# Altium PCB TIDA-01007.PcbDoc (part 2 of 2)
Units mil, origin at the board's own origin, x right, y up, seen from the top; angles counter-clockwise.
Board outline 4950 x 3450 mil, 2 copper layers (Top Layer, Bottom Layer), stack 62 mil thick; 82 components, 45 nets, 235 pads, 1732 vias.
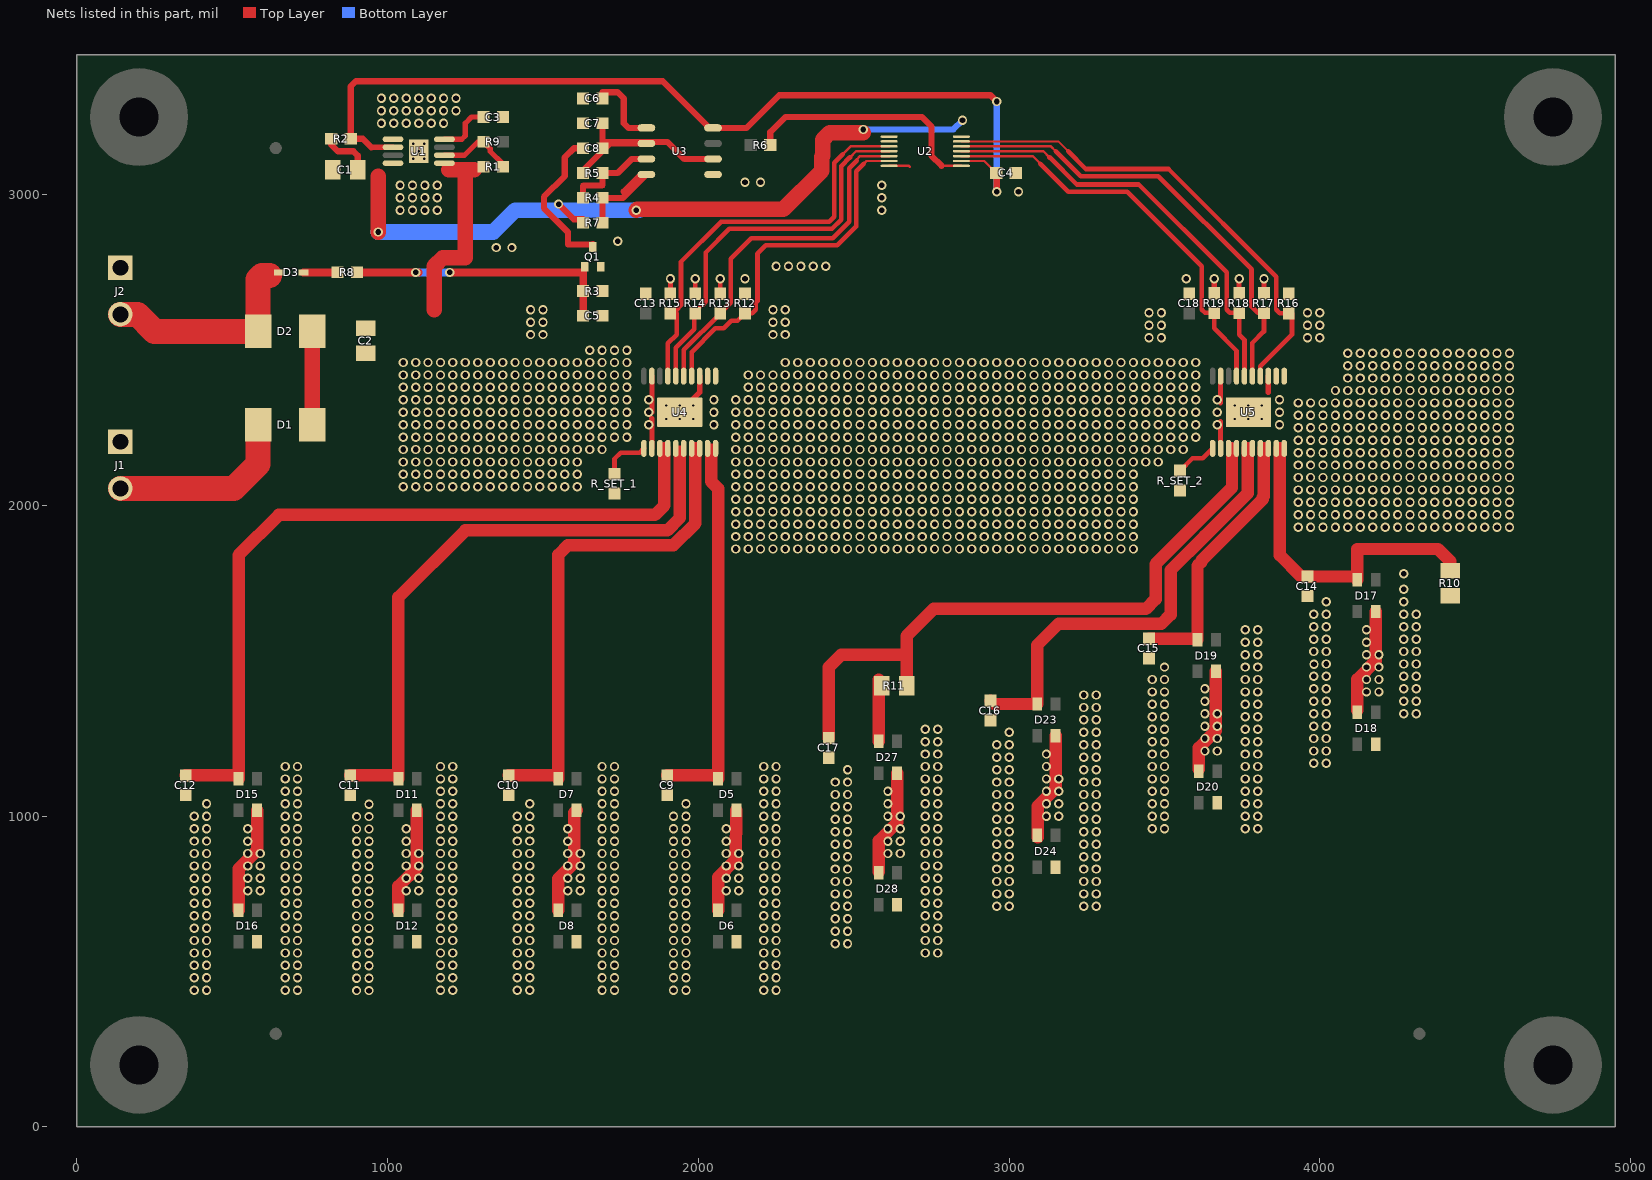
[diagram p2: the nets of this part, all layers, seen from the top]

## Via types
v1: diameter 30, hole 18, Top Layer to Bottom Layer, 1715 vias
v2: diameter 19.68, hole 7.87, Top Layer to Bottom Layer, 17 vias

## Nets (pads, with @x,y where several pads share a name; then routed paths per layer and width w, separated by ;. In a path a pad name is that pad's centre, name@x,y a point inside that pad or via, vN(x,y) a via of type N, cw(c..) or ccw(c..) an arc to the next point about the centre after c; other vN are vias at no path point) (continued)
GND: C1.2 C2.2 C3.2 C4.2 C5.2 C6.2 C7.2 C9.2 C10.2 C11.2 C12.2 C13.2 C14.2 C15.2 C16.2 C17.2 C18.2 D6.2 D8.2 D12.2 D16.2 D18.2 D20.2 D24.2 D28.2 J1.1 J2.1 Q1.2 R3.2 R10.2 R12.2 R13.2 R14.2 R15.2 R16.2 R17.2 R18.2 R19.2 R_SET_1.2 R_SET_2.2 U1.5 U1.9 U2.7 U3.1 U4.3 U4.9 U4.12 U4.21 U5.3 U5.9 U5.12 U5.21 | length 934.1
  Top Layer w7.8: U2.7@2613.86,3092.76 2677.24,3092.76 2680,3090
  Top Layer w15: R15.2@1910,2681.5 v1(1910,2730) ; R14.2@1990,2681.5 v1(1990,2730) ; R13.2@2070,2681.5 v1(2070,2730)
  Top Layer w17: 1850,2280 1850.43,2279.57 U4.12@1850.43,2183.86 ; v1@1850,2300 1850.43,2300.43 U4.9@1850.43,2416.14 ; U4.21@1940,2300 2003.98,2363.98 U4.3@2003.98,2416.14 ; R19.2@3660,2682.8 v1(3660,2730) ; U5.12@3680.43,2183.86 v1@3680.43,2270.43 ; v1@3680.43,2330.43 U5.9@3680.43,2416.14 ; R18.2@3740,2682.8 v1(3740,2730) ; R17.2@3820,2682.8 v1(3820,2730) ; 3833.98,2363.98 U5.3@3833.98,2416.14
  other v1: 900,438.98 940,438.98 377.27,440.02 417.27,440.02 670,440 710,440 1170,440 1210,440 1417.27,440.02 1457.27,440.02 1690,440 1730,440 1920,440 1960,440 2210,440 2250,440 900,478.98 940,478.98 377.27,480.02 417.27,480.02 670,480 710,480 1170,480 1210,480 1417.27,480.02 1457.27,480.02 1690,480 1730,480 1920,480 1960,480 2210,480 2250,480 900,518.98 940,518.98 377.27,520.02 417.27,520.02 670,520 710,520 1170,520 1210,520 1417.27,520.02 1457.27,520.02 1690,520 1730,520 1920,520 1960,520 2210,520 2250,520 900,558.98 940,558.98 377.27,560.02 417.27,560.02 670,560 710,560 1170,560 1210,560 1417.27,560.02 1457.27,560.02 1690,560 1730,560 1920,560 1960,560 2210,560 2250,560 2730,560 2770,560 2440,590 2480,590 900,598.98 940,598.98 377.27,600.02 417.27,600.02 670,600 710,600 1170,600 1210,600 1417.27,600.02 1457.27,600.02 1690,600 1730,600 1920,600 1960,600 2210,600 2250,600 2730,600 2770,600 2440,630 2480,630 900,638.98 940,638.98 377.27,640.02 417.27,640.02 670,640 710,640 1170,640 1210,640 1417.27,640.02 1457.27,640.02 1690,640 1730,640 1920,640 1960,640 2210,640 2250,640 2730,640 2770,640 2440,670 2480,670 900,678.98 940,678.98 377.27,680.02 417.27,680.02 670,680 710,680 1170,680 1210,680 1417.27,680.02 1457.27,680.02 1690,680 1730,680 1920,680 1960,680 2210,680 2250,680 2730,680 2770,680 2440,710 2480,710 2960,710 3000,710 3240,710 3280,710 900,718.98 940,718.98 377.27,720.02 417.27,720.02 670,720 710,720 1170,720 1210,720 1417.27,720.02 1457.27,720.02 1690,720 1730,720 1920,720 1960,720 2210,720 2250,720 2730,720 2770,720 2440,750 2480,750 2960,750 3000,750 3240,750 3280,750 900,758.98 940,758.98 377.27,760.02 417.27,760.02 670,760 710,760 1170,760 1210,760 1417.27,760.02 1457.27,760.02 1690,760 1730,760 1920,760 1960,760 2210,760 2250,760 2730,760 2770,760 2440,790 2480,790 2960,790 3000,790 3240,790 3280,790 900,798.98 940,798.98 377.27,800.02 417.27,800.02 670,800 710,800 1170,800 1210,800 1417.27,800.02 1457.27,800.02 1690,800 1730,800 1920,800 1960,800 2210,800 2250,800 2730,800 2770,800 2440,830 2480,830 2960,830 3000,830 3240,830 3280,830 900,838.98 940,838.98 377.27,840.02 417.27,840.02 670,840 710,840 1170,840 1210,840 1417.27,840.02 1457.27,840.02 1690,840 1730,840 1920,840 1960,840 2210,840 2250,840 2730,840 2770,840 2440,870 2480,870 2960,870 3000,870 3240,870 3280,870 900,878.98 940,878.98 377.27,880.02 417.27,880.02 670,880 710,880 1170,880 1210,880 1417.27,880.02 1457.27,880.02 1690,880 1730,880 1920,880 1960,880 2210,880 2250,880 2730,880 2770,880 2440,910 2480,910 2960,910 3000,910 3240,910 3280,910 900,918.98 940,918.98 377.27,920.02 417.27,920.02 670,920 710,920 1170,920 1210,920 1417.27,920.02 1457.27,920.02 1690,920 1730,920 1920,920 1960,920 2210,920 2250,920 2730,920 2770,920 2440,950 2480,950 2960,950 3000,950 3240,950 3280,950 900,958.98 940,958.98 377.27,960.02 417.27,960.02 670,960 710,960 1170,960 1210,960 1417.27,960.02 1457.27,960.02 1690,960 1730,960 1920,960 1960,960 2210,960 2250,960 2730,960 2770,960 3460,960 3500,960 3760,960 3800,960 2440,990 2480,990 2960,990 3000,990 3240,990 3280,990 900,998.98 940,998.98 377.27,1000.02 417.27,1000.02 670,1000 710,1000 1170,1000 1210,1000 1417.27,1000.02 1457.27,1000.02 1690,1000 1730,1000 1920,1000 1960,1000 2210,1000 2250,1000 2730,1000 2770,1000 3460,1000 3500,1000 3760,1000 3800,1000 2440,1030 2480,1030 2960,1030 3000,1030 3240,1030 3280,1030 940,1038.98 417.27,1040.02 670,1040 710,1040 1170,1040 1210,1040 1457.27,1040.02 1690,1040 1730,1040 1960,1040 2210,1040 2250,1040 2730,1040 2770,1040 3460,1040 3500,1040 3760,1040 3800,1040 2440,1070 2480,1070 2960,1070 3000,1070 3240,1070 3280,1070 670,1080 710,1080 1170,1080 1210,1080 1690,1080 1730,1080 2210,1080 2250,1080 2730,1080 2770,1080 3460,1080 3500,1080 3760,1080 3800,1080 2440,1110 2480,1110 2960,1110 3000,1110 3240,1110 3280,1110 670,1120 710,1120 1170,1120 1210,1120 1690,1120 1730,1120 2210,1120 2250,1120 2730,1120 2770,1120 3460,1120 3500,1120 3760,1120 3800,1120 2480,1150 2960,1150 3000,1150 3240,1150 3280,1150 670,1160 710,1160 1170,1160 1210,1160 1690,1160 1730,1160 2210,1160 2250,1160 2730,1160 2770,1160 3460,1160 3500,1160 3760,1160 3800,1160 3980,1170 4020,1170 2960,1190 3000,1190 3240,1190 3280,1190 2730,1200 2770,1200 3460,1200 3500,1200 3760,1200 3800,1200 3980,1210 4020,1210 2960,1230 3000,1230 3240,1230 3280,1230 2730,1240 2770,1240 3460,1240 3500,1240 3760,1240 3800,1240 3980,1250 4020,1250 3000,1270 3240,1270 3280,1270 2730,1280 2770,1280 3460,1280 3500,1280 3760,1280 3800,1280 3980,1290 4020,1290 3240,1310 3280,1310 3460,1320 3500,1320 3760,1320 3800,1320 3980,1330 4020,1330 4270,1330 4310,1330 3240,1350 3280,1350 3460,1360 3500,1360 3760,1360 3800,1360 3980,1370 4020,1370 4270,1370 4310,1370 3240,1390 3280,1390 3460,1400 3500,1400 3760,1400 3800,1400 3980,1410 4020,1410 4270,1410 4310,1410 3460,1440 3500,1440 3760,1440 3800,1440 3980,1450 4020,1450 4270,1450 4310,1450 3500,1480 3760,1480 3800,1480 3981,1489.08 4020,1490 4270,1490 4310,1490 3760,1520 3800,1520 3980,1530 4020,1530 4270,1530 4310,1530 3760,1560 3800,1560 3980,1570 4020,1570 4270,1570 4310,1570 3760,1600 3800,1600 3980,1610 4020,1610 4270,1610 4310,1610 3980,1650 4020,1650 4270,1650 4310,1650 4020,1690 4270,1690 4270,1730 4270,1780 2120,1860 2160,1860 2200,1860 2240,1860 2280,1860 2320,1860 2360,1860 2400,1860 2440,1860 2480,1860 2520,1860 2560,1860 2600,1860 2640,1860 2680,1860 2720,1860 2760,1860 2800,1860 2840,1860 2880,1860 2920,1860 2960,1860 3000,1860 3040,1860 3080,1860 3120,1860 3160,1860 3200,1860 3240,1860 3280,1860 3320,1860 3360,1860 3400,1860 2120,1900 2160,1900 2200,1900 2240,1900 2280,1900 2320,1900 2360,1900 2400,1900 2440,1900 2480,1900 2520,1900 2560,1900 2600,1900 2640,1900 2680,1900 2720,1900 2760,1900 2800,1900 2840,1900 2880,1900 2920,1900 2960,1900 3000,1900 3040,1900 3080,1900 3120,1900 3160,1900 3200,1900 3240,1900 3280,1900 3320,1900 3360,1900 3400,1900 3930,1930 3970,1930 4010,1930 4050,1930 4090,1930 4130,1930 4170,1930 4210,1930 4250,1930 4290,1930 4330,1930 4370,1930 4410,1930 4450,1930 4490,1930 4530,1930 4570,1930 4610,1930 2120,1940 2160,1940 2200,1940 2240,1940 2280,1940 2320,1940 2360,1940 2400,1940 2440,1940 2480,1940 2520,1940 2560,1940 2600,1940 2640,1940 2680,1940 2720,1940 2760,1940 2800,1940 2840,1940 2880,1940 2920,1940 2960,1940 3000,1940 3040,1940 3080,1940 3120,1940 3160,1940 3200,1940 3240,1940 3280,1940 3320,1940 3360,1940 3400,1940 3930,1970 3970,1970 4010,1970 4050,1970 4090,1970 4130,1970 4170,1970 4210,1970 4250,1970 4290,1970 4330,1970 4370,1970 4410,1970 4450,1970 4490,1970 4530,1970 4570,1970 4610,1970 2120,1980 2160,1980 2200,1980 2240,1980 2280,1980 2320,1980 2360,1980 2400,1980 2440,1980 2480,1980 2520,1980 2560,1980 2600,1980 2640,1980 2680,1980 2720,1980 2760,1980 2800,1980 2840,1980 2880,1980 2920,1980 2960,1980 3000,1980 3040,1980 3080,1980 3120,1980 3160,1980 3200,1980 3240,1980 3280,1980 3320,1980 3360,1980 3400,1980 3930,2010 3970,2010 4010,2010 4050,2010 4090,2010 4130,2010 4170,2010 4210,2010 4250,2010 4290,2010 4330,2010 4370,2010 4410,2010 4450,2010 4490,2010 4530,2010 4570,2010 4610,2010 2120,2020 2160,2020 2200,2020 2240,2020 2280,2020 2320,2020 2360,2020 2400,2020 2440,2020 2480,2020 2520,2020 2560,2020 2600,2020 2640,2020 2680,2020 2720,2020 2760,2020 2800,2020 2840,2020 2880,2020 2920,2020 2960,2020 3000,2020 3040,2020 3080,2020 3120,2020 3160,2020 3200,2020 3240,2020 3280,2020 3320,2020 3360,2020 3400,2020 3930,2050 3970,2050 4010,2050 4050,2050 4090,2050 4130,2050 4170,2050 4210,2050 4250,2050 4290,2050 4330,2050 4370,2050 4410,2050 4450,2050 4490,2050 4530,2050 4570,2050 4610,2050 1050,2060 1090,2060 1130,2060 1170,2060 1210,2060 1250,2060 1290,2060 1330,2060 1370,2060 1410,2060 1450,2060 1490,2060 1530,2060 1570,2060 1610,2060 2120,2060 2160,2060 2200,2060 2240,2060 2280,2060 2320,2060 2360,2060 2400,2060 2440,2060 2480,2060 2520,2060 2560,2060 2600,2060 2640,2060 2680,2060 2720,2060 2760,2060 2800,2060 2840,2060 2880,2060 2920,2060 2960,2060 3000,2060 3040,2060 3080,2060 3120,2060 3160,2060 3200,2060 3240,2060 3280,2060 3320,2060 3360,2060 3400,2060 3930,2090 3970,2090 4010,2090 4050,2090 4090,2090 4130,2090 4170,2090 4210,2090 4250,2090 4290,2090 4330,2090 4370,2090 4410,2090 4450,2090 4490,2090 4530,2090 4570,2090 4610,2090 1050,2100 1090,2100 1130,2100 1170,2100 1210,2100 1250,2100 1290,2100 1330,2100 1370,2100 1410,2100 1450,2100 1490,2100 1530,2100 1570,2100 1610,2100 2120,2100 2160,2100 2200,2100 2240,2100 2280,2100 2320,2100 2360,2100 2400,2100 2440,2100 2480,2100 2520,2100 2560,2100 2600,2100 2640,2100 2680,2100 2720,2100 2760,2100 2800,2100 2840,2100 2880,2100 2920,2100 2960,2100 3000,2100 3040,2100 3080,2100 3120,2100 3160,2100 3200,2100 3240,2100 3280,2100 3320,2100 3360,2100 3400,2100 3930,2130 3970,2130 4010,2130 4050,2130 4090,2130 4130,2130 4170,2130 4210,2130 4250,2130 4290,2130 4330,2130 4370,2130 4410,2130 4450,2130 4490,2130 4530,2130 4570,2130 4610,2130 1050,2140 1090,2140 1130,2140 1170,2140 1210,2140 1250,2140 1290,2140 1330,2140 1370,2140 1410,2140 1450,2140 1490,2140 1530,2140 1570,2140 1610,2140 2120,2140 2160,2140 2200,2140 2240,2140 2280,2140 2320,2140 2360,2140 2400,2140 2440,2140 2480,2140 2520,2140 2560,2140 2600,2140 2640,2140 2680,2140 2720,2140 2760,2140 2800,2140 2840,2140 2880,2140 2920,2140 2960,2140 3000,2140 3040,2140 3080,2140 3120,2140 3160,2140 3200,2140 3240,2140 3280,2140 3320,2140 3360,2140 3400,2140 3440,2140 3480,2140 3930,2170 3970,2170 4010,2170 4050,2170 4090,2170 4130,2170 4170,2170 4210,2170 4250,2170 4290,2170 4330,2170 4370,2170 4410,2170 4450,2170 4490,2170 4530,2170 4570,2170 4610,2170 1050,2180 1090,2180 1130,2180 1170,2180 1210,2180 1250,2180 1290,2180 1330,2180 1370,2180 1410,2180 1450,2180 1490,2180 1530,2180 1570,2180 1610,2180 1650,2180 1690,2180 2120,2180 2160,2180 2200,2180 2240,2180 2280,2180 2320,2180 2360,2180 2400,2180 2440,2180 2480,2180 2520,2180 2560,2180 2600,2180 2640,2180 2680,2180 2720,2180 2760,2180 2800,2180 2840,2180 2880,2180 2920,2180 2960,2180 3000,2180 3040,2180 3080,2180 3120,2180 3160,2180 3200,2180 3240,2180 3280,2180 3320,2180 3360,2180 3400,2180 3440,2180 3480,2180 3520,2180 3560,2180 3930,2210 3970,2210 4010,2210 4050,2210 4090,2210 4130,2210 4170,2210 4210,2210 4250,2210 4290,2210 4330,2210 4370,2210 4410,2210 4450,2210 4490,2210 4530,2210 4570,2210 4610,2210 1050,2220 1090,2220 1130,2220 1170,2220 1210,2220 1250,2220 1290,2220 1330,2220 1370,2220 1410,2220 1450,2220 1490,2220 1530,2220 1570,2220 1610,2220 1650,2220 1690,2220 1730,2220 1770,2220 2120,2220 2160,2220 2200,2220 2240,2220 2280,2220 2320,2220 2360,2220 2400,2220 2440,2220 2480,2220 2520,2220 2560,2220 2600,2220 2640,2220 2680,2220 2720,2220 2760,2220 2800,2220 2840,2220 2880,2220 2920,2220 2960,2220 3000,2220 3040,2220 3080,2220 3120,2220 3160,2220 3200,2220 3240,2220 3280,2220 3320,2220 3360,2220 3400,2220 3440,2220 3480,2220 3520,2220 3560,2220 3600,2220 3930,2250 3970,2250 4010,2250 4050,2250 4090,2250 4130,2250 4170,2250 4210,2250 4250,2250 4290,2250 4330,2250 4370,2250 4410,2250 4450,2250 4490,2250 4530,2250 4570,2250 4610,2250 1050,2260 1090,2260 1130,2260 1170,2260 1210,2260 1250,2260 1290,2260 1330,2260 1370,2260 1410,2260 1450,2260 1490,2260 1530,2260 1570,2260 1610,2260 1650,2260 1690,2260 1730,2260 1770,2260 1840,2260 2050,2260 2120,2260 2160,2260 2200,2260 2240,2260 2280,2260 2320,2260 2360,2260 2400,2260 2440,2260 2480,2260 2520,2260 2560,2260 2600,2260 2640,2260 2680,2260 2720,2260 2760,2260 2800,2260 2840,2260 2880,2260 2920,2260 2960,2260 3000,2260 3040,2260 3080,2260 3120,2260 3160,2260 3200,2260 3240,2260 3280,2260 3320,2260 3360,2260 3400,2260 3440,2260 3480,2260 3520,2260 3560,2260 3600,2260 3670,2260 3870,2260 3930,2290 3970,2290 4010,2290 4050,2290 4090,2290 4130,2290 4170,2290 4210,2290 4250,2290 4290,2290 4330,2290 4370,2290 4410,2290 4450,2290 4490,2290 4530,2290 4570,2290 4610,2290 1050,2300 1090,2300 1130,2300 1170,2300 1210,2300 1250,2300 1290,2300 1330,2300 1370,2300 1410,2300 1450,2300 1490,2300 1530,2300 1570,2300 1610,2300 1650,2300 1690,2300 1730,2300 1770,2300 1840,2300 2050,2300 2120,2300 2160,2300 2200,2300 2240,2300 2280,2300 2320,2300 2360,2300 2400,2300 2440,2300 2480,2300 2520,2300 2560,2300 2600,2300 2640,2300 2680,2300 2720,2300 2760,2300 2800,2300 2840,2300 2880,2300 2920,2300 2960,2300 3000,2300 3040,2300 3080,2300 3120,2300 3160,2300 3200,2300 3240,2300 3280,2300 3320,2300 3360,2300 3400,2300 3440,2300 3480,2300 3520,2300 3560,2300 3600,2300 3670,2300 3870,2300 3930,2330 3970,2330 4010,2330 4050,2330 4090,2330 4130,2330 4170,2330 4210,2330 4250,2330 4290,2330 4330,2330 4370,2330 4410,2330 4450,2330 4490,2330 4530,2330 4570,2330 4610,2330 1050,2340 1090,2340 1130,2340 1170,2340 1210,2340 1250,2340 1290,2340 1330,2340 1370,2340 1410,2340 1450,2340 1490,2340 1530,2340 1570,2340 1610,2340 1650,2340 1690,2340 1730,2340 1770,2340 1840,2340 2050,2340 2120,2340 2160,2340 2200,2340 2240,2340 2280,2340 2320,2340 2360,2340 2400,2340 2440,2340 2480,2340 2520,2340 2560,2340 2600,2340 2640,2340 2680,2340 2720,2340 2760,2340 2800,2340 2840,2340 2880,2340 2920,2340 2960,2340 3000,2340 3040,2340 3080,2340 3120,2340 3160,2340 3200,2340 3240,2340 3280,2340 3320,2340 3360,2340 3400,2340 3440,2340 3480,2340 3520,2340 3560,2340 3600,2340 3670,2340 3870,2340 4050,2370 4090,2370 4130,2370 4170,2370 4210,2370 4250,2370 4290,2370 4330,2370 4370,2370 4410,2370 4450,2370 4490,2370 4530,2370 4570,2370 4610,2370 1050,2380 1090,2380 1130,2380 1170,2380 1210,2380 1250,2380 1290,2380 1330,2380 1370,2380 1410,2380 1450,2380 1490,2380 1530,2380 1570,2380 1610,2380 1650,2380 1690,2380 1730,2380 1770,2380 2160,2380 2200,2380 2240,2380 2280,2380 2320,2380 2360,2380 2400,2380 2440,2380 2480,2380 2520,2380 2560,2380 2600,2380 2640,2380 2680,2380 2720,2380 2760,2380 2800,2380 2840,2380 2880,2380 2920,2380 2960,2380 3000,2380 3040,2380 3080,2380 3120,2380 3160,2380 3200,2380 3240,2380 3280,2380 3320,2380 3360,2380 3400,2380 3440,2380 3480,2380 3520,2380 3560,2380 3600,2380 4090,2410 4130,2410 4170,2410 4210,2410 4250,2410 4290,2410 4330,2410 4370,2410 4410,2410 4450,2410 4490,2410 4530,2410 4570,2410 4610,2410 1050,2420 1090,2420 1130,2420 1170,2420 1210,2420 1250,2420 1290,2420 1330,2420 1370,2420 1410,2420 1450,2420 1490,2420 1530,2420 1570,2420 1610,2420 1650,2420 1690,2420 1730,2420 1770,2420 2160,2420 2200,2420 2240,2420 2280,2420 2320,2420 2360,2420 2400,2420 2440,2420 2480,2420 2520,2420 2560,2420 2600,2420 2640,2420 2680,2420 2720,2420 2760,2420 2800,2420 2840,2420 2880,2420 2920,2420 2960,2420 3000,2420 3040,2420 3080,2420 3120,2420 3160,2420 3200,2420 3240,2420 3280,2420 3320,2420 3360,2420 3400,2420 3440,2420 3480,2420 3520,2420 3560,2420 3600,2420 4090,2450 4130,2450 4170,2450 4210,2450 4250,2450 4290,2450 4330,2450 4370,2450 4410,2450 4450,2450 4490,2450 4530,2450 4570,2450 4610,2450 1050,2460 1090,2460 1130,2460 1170,2460 1210,2460 1250,2460 1290,2460 1330,2460 1370,2460 1410,2460 1450,2460 1490,2460 1530,2460 1570,2460 1610,2460 1650,2460 1690,2460 1730,2460 1770,2460 2280,2460 2320,2460 2360,2460 2400,2460 2440,2460 2480,2460 2520,2460 2560,2460 2600,2460 2640,2460 2680,2460 2720,2460 2760,2460 2800,2460 2840,2460 2880,2460 2920,2460 2960,2460 3000,2460 3040,2460 3080,2460 3120,2460 3160,2460 3200,2460 3240,2460 3280,2460 3320,2460 3360,2460 3400,2460 3440,2460 3480,2460 3520,2460 3560,2460 3600,2460 4090,2490 4130,2490 4170,2490 4210,2490 4250,2490 4290,2490 4330,2490 4370,2490 4410,2490 4450,2490 4490,2490 4530,2490 4570,2490 4610,2490 1650,2500 1690,2500 1730,2500 1770,2500 2150,2730 3570,2730 2250,2770 2290,2770 2330,2770 2370,2770 2410,2770 1350,2830 1400,2830 1740,2850 1040,2950 1080,2950 1120,2950 1160,2950 2590,2950 1040,2990 1080,2990 1120,2990 1160,2990 2590,2990 3030,3010 1040,3030 1080,3030 1120,3030 1160,3030 2590,3030 2150,3040 2200,3040 980,3230 1020,3230 1060,3230 1100,3230 1140,3230 1180,3230 980,3270 1020,3270 1060,3270 1100,3270 1140,3270 1180,3270 1220,3270 980,3310 1020,3310 1060,3310 1100,3310 1140,3310 1180,3310 1220,3310
  other v2: 1896.69,2278.35 1940,2278.35 1983.31,2278.35 3726.69,2278.35 3770,2278.35 3813.31,2278.35 1896.69,2321.65 1940,2321.65 1983.31,2321.65 3726.69,2321.65 3770,2321.65 3813.31,2321.65 1082.28,3116.38 1117.72,3116.38 1100,3140 1082.28,3163.62 1117.72,3163.62
LDOEN: R1.2 R9.1 U1.2 | length 249.6
  Top Layer w17: U1.2@1182.68,3127.2 1247.2,3127.2 1290,3170 R9.1@1308.5,3170 1330,3148.5 1330,3140 1371.5,3098.5 R1.2@1371.5,3090
NetC3_1: C3.1 U1.4 | length 178.9
  Top Layer w17: U1.4@1182.68,3178.39 1238.39,3178.39 1250,3190 1250,3230 1270,3250 C3.1@1308.5,3250
NetC4_1: C4.1 R2.1 U1.6 U2.9 U3.4 | length 2983.8
  Top Layer w7.8: U2.9@2846.14,3108.5 2920,3108.5 C4.1@2958.5,3070
  Top Layer w17: 947.2,3152.8 U1.6@1017.32,3152.8
  Top Layer w20: 947.2,3152.8 920,3180 R2.1@881.5,3180 881.5,3348.5 897.99,3365 1885,3365 2035,3215 U3.4@2047.28,3215 2155,3215 2260,3320 2940,3320 v1(2960,3300) ; C4.1@2958.5,3070 2960,3068.5 v1(2960,3010)
  Bottom Layer w20: v1@2960,3020 v1(2960,3300)
NetC5_1: C5.1 Q1.1 R3.1 R8.2 | length 878.2
  Top Layer w25: R8.2@901.5,2750 v1(1090,2750) v1@1100,2750 ; v1(1200,2750) 1629.68,2750 R3.1@1629.68,2690 ; C5.1@1629.8,2620 R3.1@1629.8,2700
  Bottom Layer w25: v1(1090,2750) v1(1200,2750)
NetC6_1: C6.1 U3.5 | length 235.7
  Top Layer w20: 1691.5,3330 1740,3330 1760,3310 1760,3230 1775,3215 U3.5@1832.72,3215
NetC7_1: C7.1 C8.1 R5.1 U3.2 U3.6 | length 706.9
  Top Layer w20: R5.1@1628.41,3069.73 1628.41,3077.55 1715.87,3165 U3.6@1832.72,3165 ; C8.1@1691.41,3149.73 C7.1@1691.41,3229.73 ; 1691.5,3170 1900,3170 1955,3115 U3.2@2047.28,3115
NetC8_2: C8.2 Q1.3 | length 500.2
  Top Layer w20: C8.2@1628.41,3149.73 1599.73,3149.73 1570,3120 1570,3060 1503,2993 1503,2957 1580,2880 1580,2840 1660,2840 Q1.3@1660,2831.5 ; Q1.3@1660,2841.5 Q1.3@1661.3,2841.5
NetD3_1: D3.1 R8.1 | length 109.1
  Top Layer w25: D3.1@729.37,2750 R8.1@838.5,2750
NetD5_2: D5.2 D6.4 | length 344.2
  Top Layer w40: D6.4@2063.33,698.11 2063.33,803.33 2120,860 D5.2@2122.38,1018.82
  other v1: 2090,760 2130,760 2090,800 2130,800 2090,840 2130,840 2090,880 2130,880 2090,920 2090,960
NetD7_2: D7.2 D8.4 | length 345.2
  Top Layer w40: D8.4@1549.04,698.11 1549.04,799.04 1600,850 1600,1010.72 D7.2@1608.1,1018.82
  other v1: 1580,760 1620,760 1580,800 1620,800 1580,840 1620,840 1580,880 1620,880 1580,920 1580,960
NetD11_2: D11.2 D12.4 | length 345.2
  Top Layer w40: D12.4@1034.76,698.11 1034.76,774.76 1093.81,833.81 D11.2@1093.81,1018.82
  other v1: 1060,760 1100,760 1060,800 1100,800 1060,840 1100,840 1060,880 1100,880 1060,920 1060,960
NetD15_2: D15.2 D16.4 | length 345.6
  Top Layer w40: D16.4@520.47,698.11 520.47,830.47 580,890 580,1018.35 D15.2@579.53,1018.82
  other v1: 550,760 590,760 550,800 590,800 550,840 590,840 550,880 590,880 550,920 550,960
NetD17_2: D17.2 D18.4 | length 342.1
  Top Layer w40: D18.4@4120.47,1341.18 4120.47,1440.47 4179.53,1499.53 D17.2@4179.53,1658.82
  other v1: 4150,1400 4190,1400 4150,1440 4190,1440 4150,1480 4190,1480 4150,1520 4190,1520 4150,1560 4150,1600
NetD19_2: D19.2 D20.4 | length 337.5
  Top Layer w40: D20.4@3610.47,1151.18 3610.47,1220.47 3665.24,1275.24 D19.2@3665.24,1465.95
  other v1: 3630,1210 3670,1210 3630,1250 3670,1250 3630,1290 3670,1290 3630,1330 3670,1330 3630,1370 3630,1410
NetD23_2: D23.2 D24.4 | length 350.6
  Top Layer w40: D24.4@3091.9,932.1 3091.9,1031.9 3149.53,1089.53 D23.2@3149.53,1258.82
  other v1: 3120,1000 3160,1000 3120,1040 3160,1040 3120,1080 3160,1080 3120,1120 3160,1120 3120,1160 3120,1200
NetD27_2: D27.2 D28.4 | length 342.5
  Top Layer w40: D28.4@2580.47,821.18 2580.47,920.47 2640,980 2640,1138.35 D27.2@2639.53,1138.82
  other v1: 2610,880 2650,880 2610,920 2650,920 2610,960 2650,960 2610,1000 2650,1000 2610,1040 2610,1080
NetD27_4: D27.4 R11.2 | length 199
  Top Layer w40: R11.2@2580,1440 2580.47,1439.53 D27.4@2580.47,1241.18
NetR4_1: R4.1 R7.2 U3.8 | length 348
  Top Layer w20: R7.2@1691.41,2909.73 R4.1@1691.41,2989.73 1757.45,2989.73 U3.8@1832.72,3065 1815,3065 1760,3010
NetR4_2: R4.2 R5.2 U3.7 | length 301.3
  Top Layer w20: R4.2@1628.41,2989.73 1628.41,3028.23 1629.91,3029.73 1689.91,3029.73 1691.41,3031.23 R5.2@1691.41,3069.73 1739.73,3069.73 1785,3115 U3.7@1832.72,3115
NetR_SET_1_1: R_SET_1.1 U4.11 | length 157.4
  Top Layer w15: R_SET_1.1@1730,2101.5 1730,2150 1750,2170 1810.98,2170 U4.11@1824.84,2183.86
NetR_SET_2_1: R_SET_2.1 U5.11 | length 134.8
  Top Layer w15: R_SET_2.1@3550,2111.5 3590,2151.5 3622.48,2151.5 U5.11@3654.84,2183.86
OUT1: C12.1 D15.4 U4.13 U4.14 | length 2499.1
  Top Layer w40: C12.1@350,1131.5 D15.4@510.16,1131.5 ; D15.4@520.47,1121.18 520.47,1840.47 650,1970 1860,1970 1890.47,2000.47 1890.47,2183.86
OUT2: C11.1 D11.4 U4.15 U4.16 | length 1952.6
  Top Layer w40: C11.1@880,1131.5 D11.4@1024.44,1131.5 ; D11.4@1034.76,1121.18 1034.76,1704.76 1250,1920 1900,1920 1940,1960 1940,2173.61
OUT3: C10.1 D7.4 U4.17 U4.18 | length 1593.3
  Top Layer w40: C10.1@1390,1131.5 D7.4@1538.73,1131.5 ; D7.4@1549.04,1121.18 1549.04,1841.17 1580,1872.13 1919.83,1872.13 1990,1942.3 1990,2183.39 1989.53,2183.86
OUT4: C9.1 D5.4 U4.19 U4.20 | length 1235.8
  Top Layer w40: C9.1@1900,1131.5 2053.01,1131.5 D5.4@2063.33,1121.18 2063.33,2054.54 2040.71,2077.17 2040.71,2180
OUT5: C17.1 R11.1 U5.13 U5.14 | length 2092.6
  Top Layer w40: C17.1@2420,1251.5 2420,1480 2460,1520 2670,1520 ; R11.1@2670,1420 2670,1520 ; 3717.17,2183.86 3717.17,2057.17 3471.5,1811.5 3471.5,1698.74 3440,1667.24 2757.24,1667.24 2670,1580 2670,1520
OUT6: C16.1 D23.4 U5.15 U5.16 | length 1452.2
  Top Layer w40: C16.1@2940,1371.5 2950.32,1361.18 D23.4@3090.47,1361.18 3090.47,1550.47 3159.37,1619.37 3490,1619.37 3519.37,1648.74 3519.37,1791.5 3630,1902.13 3630.47,1902.13 3768.35,2040 3768.35,2183.86
OUT7: C15.1 D19.4 U5.17 U5.18 | length 856.9
  Top Layer w40: C15.1@3450,1571.5 D19.4@3603,1571.5 ; D19.4@3606.19,1568.31 3606.19,1806.19 3620,1820 3620,1823.95 3816.22,2020.17 3816.22,2026.69 3819.53,2030 3819.53,2183.86
OUT8: C14.1 D17.4 R10.1 U5.19 U5.20 | length 1048.4
  Top Layer w40: 3870.71,2183.86 3870.71,1840 3939.21,1771.5 C14.1@3960,1771.5 4101.97,1771.5 ; D17.4@4120.47,1761.18 4120.47,1860 4380,1860 4420,1820 R10.1@4420,1790
PWM1: R15.1 U2.3 U4.7 | length 1324.1
  Top Layer w7.8: 2464.25,3130 2490,3155.75 U2.3@2613.86,3155.75
  Top Layer w15: U4.7@1901.61,2416.14 1901.61,2521.61 1930,2550 1930,2618.5 ; R15.1@1910,2618.5 1921.5,2630 1930,2630 1944.07,2644.07 1944.07,2784.07 2072.87,2912.87 2420.53,2912.87 2437.13,2929.47 2437.13,3102.87 2464.25,3130
PWM2: R14.1 U2.4 U4.6 | length 1268.2
  Top Layer w7.8: 2487.65,3120 2507.65,3140 U2.4@2613.86,3140
  Top Layer w15: U4.6@1927.2,2416.14 1927.2,2507.2 1987.13,2567.13 1987.13,2618.5 R14.1@1990,2618.5 1990,2625.93 2010.51,2646.44 2015.07,2646.44 2024.07,2655.44 2024.07,2814.07 2100,2890 2430,2890 2460,2920 2460,3092.35 2487.65,3120
PWM3: R13.1 U2.5 U4.5 | length 1190.6
  Top Layer w7.8: 2510,3110 2510,3114.25 2520,3124.25 U2.5@2613.86,3124.25
  Top Layer w15: U4.5@1952.8,2416.14 1952.8,2500.45 2070,2617.65 R13.1@2070,2618.5 2104.07,2652.58 2104.07,2794.07 2170,2860 2432.35,2860 2485,2912.65 2485,3085 2510,3110
PWM4: R12.1 U2.6 U4.4 | length 1174
  Top Layer w7.8: 2532.35,3100 2540.85,3108.5 U2.6@2613.86,3108.5
  Top Layer w15: U4.4@1978.39,2416.14 1978.39,2493.69 2054.7,2570 2081.62,2570 2105.89,2594.26 2125.76,2594.26 R12.1@2150,2618.5 2173.13,2618.5 2184.63,2630 2184.63,2651.74 2190,2657.12 2190,2810 2217.13,2837.13 2447.13,2837.13 2507.87,2897.87 2507.87,3075.53 2532.35,3100
PWM5: R19.1 U2.10 U5.7 | length 1338.1
  Top Layer w7.8: U2.10@2846.14,3124.25 3075.75,3124.25 3100,3100
  Top Layer w15: 3100,3100 3190,3010 3380,3010 3620,2770 3620,2630 3630.2,2619.8 R19.1@3660,2619.8 3660,2570 3731.61,2498.39 U5.7@3731.61,2416.14
PWM6: R18.1 U2.11 U5.6 | length 1390.4
  Top Layer w7.8: U2.11@2846.14,3140 3110,3140 3130,3120
  Top Layer w15: 3130,3120 3217.13,3032.87 3417.13,3032.87 3700,2750 3700,2630 3710.2,2619.8 R18.1@3740,2619.8 3740,2550 3757.2,2532.8 U5.6@3757.2,2416.14
PWM7: R17.1 U2.12 U5.5 | length 1485.2
  Top Layer w7.8: U2.12@2846.14,3155.75 3134.25,3155.75 3150,3140
  Top Layer w15: 3150,3140 3230,3060 3480,3060 3780,2760 3780,2640 3800.2,2619.8 R17.1@3820,2619.8 3820,2560 3782.8,2522.8 U5.5@3782.8,2416.14
PWM8: R16.1 U2.13 U5.4 | length 1589.3
  Top Layer w6: U2.13@2846.14,3171.5 3158.5,3171.5 3190,3140
  Top Layer w15: 3190,3140 3247.13,3082.87 3512.83,3082.87 3860,2735.7 3860,2630 3871.5,2618.5 R16.1@3900,2618.5 ; U5.4@3808.39,2416.14 3808.39,2448.39 3910,2550 R16.1@3910,2618.5
SHIFTER_CLK: R6.1 U2.8 | length 796.7
  Top Layer w7.8: 2782.76,3092.76 U2.8@2846.14,3092.76
  Top Layer w20: R6.1@2231.5,3160 2231.5,3201.5 2280,3250 2720,3250 2750,3220 2750,3125.51 2782.76,3092.76
V_5V: C1.1 R2.2 R7.1 U1.8 U2.1 U2.2 U2.14 | length 2548.3
  Top Layer w20: R2.2@818.5,3180 818.5,3161.5 840,3140 890,3140 904.02,3125.98 C1.1@904.02,3080 ; v1(1550,2970) 1598.59,2921.41 R7.1@1628.41,2921.41 ; R7.1@1628.41,2909.73 R7.1@1628.41,2921.41 ; R7.1@1628.5,2920 1628.5,2921.41 R7.1@1628.41,2921.41
  Top Layer w50: v1(970,2880) 970,3060 ; v1(1800,2950) 1803.25,2953.25 2273.25,2953.25 2396.75,3076.75 2396.75,3122.85 2400,3126.09 2400,3177.13 2422.87,3200 v1@2530,3200
  Bottom Layer w20: v1(2530,3210) 2820,3210 v1(2850,3240)
  Bottom Layer w50: v1(970,2880) 1340,2880 1410,2950 v1(1800,2950) v1@1810,2950
V_HAZARD: D1.2 J1.2 | length 602.3
  Top Layer w80: J1.2@140,2055 505,2055 582.99,2132.99 D1.2@582.99,2260
V_IN: C2.1 D1.1 D2.1 R1.1 U1.1 U4.1 U4.2 U5.1 U5.2 | length 917.4
  Top Layer w50: D1.1@757.01,2260 D2.1@757.01,2560 ; 1150,2630 1150,2770 1177.74,2797.74 1180.04,2797.74 1180.17,2797.87 1219.83,2797.87 1219.96,2797.74 1250,2797.74 1250,3081.01 ; 1196.5,3081.01 1250,3081.01 ; 1279.01,3081.01 1250,3081.01
  other v1: 3450,2540 3490,2540 3960,2540 4000,2540 1460,2550 1500,2550 2240,2550 2280,2550 3450,2580 3490,2580 3960,2580 4000,2580 1460,2590 1500,2590 2240,2590 2280,2590 3450,2620 3490,2620 3960,2620 4000,2620 1460,2630 1500,2630 2240,2630 2280,2630
V_TURN: D2.2 D3.2 J2.2 | length 675.2
  Top Layer w80: J2.2@140,2615 195,2615 250,2560 D2.2@582.99,2560 582.99,2727.01 595.98,2740 620,2740
pads on no net: D5.1 D5.3 D6.1 D6.3 D7.1 D7.3 D8.1 D8.3 D11.1 D11.3 D12.1 D12.3 D15.1 D15.3 D16.1 D16.3 D17.1 D17.3 D18.1 D18.3 D19.1 D19.3 D20.1 D20.3 D23.1 D23.3 D24.1 D24.3 D27.1 D27.3 D28.1 D28.3 FID1.1 FID2.1 FID3.1 H1.1 H2.1 H3.1 H4.1 U1.3 U1.7 U4.10 U5.10

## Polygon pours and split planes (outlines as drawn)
GND on Top Layer "Top Layer-No Net" (solid, remove dead copper, pour order 4): 0,3450 4940,3450 4940,40 4920,20 4910,10 -10,10 -10,3480
GND on Bottom Layer "Bottom Layer-No Net" (solid, remove dead copper, pour order 6): -5,3450 15,3470 4880,3470 4880,160 4940,100 4950,90 4950,40 60,40 0,-20 20,0 20,3430

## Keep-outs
Keep-Out Layer:
  lines w10: 4950,-5 0,-5 ; 4955,0 4955,3450 ; -5,0 ccw(c0,0) 0,-5 ; -5,0 ccw(c0,0) 0,-5 ; -5,0 -5,3450 ; -5,3450 cw(c0,3450) 0,3455 ; -5,3450 cw(c0,3450) 0,3455 ; 0,3455 4950,3455 ; 4950,3455 cw(c4950,3450) 4955,3450 ; 4950,3455 cw(c4950,3450) 4955,3450
  text ".Layer_Name" at 577,-858.49 h60

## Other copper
Top Layer:
  rectangle net V_IN: 720,2530 1530,2648.58
  rectangle net V_IN: 720,2170 850,2640
  rectangle net V_5V: 889.61,3069.13 1045.85,3110
  rectangle net V_5V: 2500,3170 2641.42,3200
  rectangle net OUT1: 1871.2,2160 1900,2204.31
  rectangle net OUT2: 1932.03,2160 1950,2204.31
  rectangle net OUT3: 1983.21,2160 2000,2204.31
  rectangle net OUT4: 2034.39,2160 2050,2204.31
  rectangle net OUT5: 3701.2,2160 3730,2204.31
  rectangle net OUT6: 3762.03,2160 3780,2204.31
  rectangle net OUT7: 3813.21,2160 3830,2204.31
  rectangle net OUT8: 3864.39,2160 3880,2204.31
  rectangle net V_IN: 2200,2530 3500,2640
  rectangle net V_IN: 3940,2390 4020,2650
  rectangle net V_IN: 3860,2380 4010,2453.54
  rectangle net V_IN: 2030,2390 2120,2453.54
  rectangle net V_IN: 2150,2500 2240,2580
  rectangle net V_5V: 2820,3190 2880,3260
  rectangle net NetD15_2: 469.29,739.45 630.71,977.48
  rectangle net NetD11_2: 980,740 1130,970
  rectangle net NetD7_2: 1510,739.45 1650,977.48
  rectangle net NetD5_2: 2000,739.45 2170,977.48
  rectangle net NetD27_2: 2529.29,862.52 2690.71,1097.48
  rectangle net NetD23_2: 3050,973.44 3190,1217.48
  rectangle net NetD19_2: 3555,1192.52 3710,1424.61
  rectangle net NetD17_2: 4069.29,1382.52 4220,1617.48
  rectangle net GND: 2576.46,3030 2680,3090
  rectangle net V_IN: 2040,2430 2120,2520
  rectangle net V_IN: 2080,2480 2240,2550
  text ".Layer_Name" at 577,-858.49 h60
Bottom Layer:
  rectangle net V_IN: 1430,2540 2300,2650
  rectangle net V_IN: 3430,2530 4020,2640
  rectangle net NetD15_2: 470,680 630.71,1040
  rectangle net NetD11_2: 983.58,680 1140,1040
  rectangle net NetD7_2: 1497.86,680 1650,1040
  rectangle net NetD5_2: 2010,680 2173.57,1040
  rectangle net NetD27_2: 2520,800 2690.71,1160
  rectangle net NetD23_2: 3039.29,910 3190,1280
  rectangle net NetD19_2: 3555,1130 3710,1490
  rectangle net NetD17_2: 4069.29,1320 4220,1680
  text ".Layer_Name" at 577,-858.49 h60

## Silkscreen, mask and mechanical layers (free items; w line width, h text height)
Top Overlay:
  circle w10: c1150,3069.13 r9.13
  circle w10: c2040,3010 r9.13
  circle w10: c2610,3239.13 r9.13
  circle w10: c2100,2369.13 r9.13
  circle w10: c3930,2379.13 r9.13
  text "This document can handle board shapes up to 7.9in x 10in, although" at 220,6725 h60
  text "our panel vendors top out at 7in x 10in." at 220,6600.94 h60
  text "To re-size the board shape, do the following:" at 275,6476.88 h60
  text "Select lines on M1 Board Outline and delete (easy in single layer mode...shift+s)" at 335,6352.82 h60
  text "Draw a rectangle using lines (example will be for a 4\" x 6\" board" at 335,6228.76 h60
  text "Enter Place Line mode (keyboard pl)" at 545,6104.71 h60
  text "keyboard jo to jump to origin, hit enter" at 545,5980.65 h60
  text "keyboard jl to jump to location, set x to 6000, hit enter twice" at 545,5856.59 h60
  text "keyboard jl to jump to location, set x to 6000 and y to 4000, hit enter twice" at 545,5732.53 h60
  text "keyboard jl to jump to location, set x to 0 and y to 4000, hit enter twice" at 545,5608.47 h60
  text "keyboard jo to jump to origin, hit enter" at 545,5484.41 h60
  text "Hit ESC twice to exit place line mode" at 545,5360.35 h60
  text "Select lines on M1 Board Outline" at 335,5216.3 h60
  text "Menu Design|Board Shape|Define from Selected Objects (keyboard dsd)" at 335,5112.24 h60
  text "To define a Keep-Out that mirrors the board outline:" at 220,4988.18 h60
  text "Menu Design|Board Shape|Create Primitives From Board Shape (keyboard dsp)" at 335,4864.12 h60
  text "Set the Keep-Out Layer as the layer, set width as preferred" at 545,4740.06 h60
  text "Ensure Route Tool Outline is selected, hit enter" at 545,4616 h60
  text "If you re-size the board, don't forget to move the drill table strings on the" at 220,4293 h60
  text "Drill Drawing Layer...they should be just to the right of your board shape" at 413,4187 h60
  text "GND" at 4370,3360 h40
  text "555_CLK_OUT" at 2200,3300 h40
  text "GND" at 330,2750 h40
  text "V_TURN" at 140,2420 h40
  text "GND" at 330,2200 h40
  text "V_HAZARD" at 120,1850 h40
  text "CH5_OPEN" at 2520,1570 h40
  text "CH8_SHORT_GND" at 4560,1390 h40 r90
  text "TI Design" at 800,220 h60
  text "Sequential Turn TPS92638-Q1" at 810,80 h60
  text ".Layer_Name" at 577,-858.49 h60
Bottom Overlay:
  text ".Layer_Name" at 577,-858.49 h60
Top Paste:
  text ".Layer_Name" at 577,-858.49 h60
Bottom Paste:
  text ".Layer_Name" at 577,-858.49 h60
Top Solder:
  text ".Layer_Name" at 577,-858.49 h60
  text ".Layer_Name" at 577,-858.49 h60
Bottom Solder:
  text ".Layer_Name" at 577,-858.49 h60
Drill Guide:
  text ".Layer_Name" at 577,-858.49 h60
M1 Board Outline:
  the board outline again, w10
  text ".Layer_Name" at 577,-858.49 h60
M2 Board Dimensions:
  rectangle: 0,-275 125,-150
  rectangle: 125,-400 500,-275
  lines w7: 0,-275 1000,-275 ; 125,-400 125,-150 ; 250,-400 250,-150 ; 500,-400 500,-150 ; 750,-400 750,-150 ; 0,-400 1000,-400 1000,-150 0,-150 0,-400
  text ".Layer_Name" at 577,-858.49 h60
M3 3D STEP Top:
  text ".Layer_Name" at 577,-858.49 h60
M4 3D STEP Bottom:
  text ".Layer_Name" at 577,-858.49 h60
M5 Assembly Top:
  lines w10: -292,-930.17 6308,-930.17 ; -292,-726.83 6310,-726.83 ; -292,-523.5 -292,-1133.5 3713,-1133.5 6310,-1133.5 6310,-523.5 -291.5,-523.5 -291.5,-1133.5 1284,-1133.5 ; 2173,-1133.5 2173,-523.5 ; 3440,-726.83 3440,-523.5 ; 4280,-726.83 4280,-523.5 ; 4902,-1140 4902,-937.17
  text "COMPONENTS MARKED 'DNP' SHOULD NOT BE POPULATED." at 1153.5,-318.5 h60
  text "ASSEMBLY VARIANT:" at 1153,-434 h60
  text ".VariantName" at 2189,-434 h60
  text "PCB VIEWED FROM TOP SIDE" at -228.5,-655.67 h60
  text "BOARD #:" at 2248,-655.67 h60
  text ".PRJ_Number" at 2793.5,-655.67 h60
  text "REV:" at 3638,-655.67 h60
  text ".PCB_Rev" at 3929.5,-655.67 h60
  text "SVN REV:" at 4476,-655.67 h60
  text ".VersionControl_RevNumber" at 4982,-655.67 h60
  text "TID #:" at 2248,-859 h60
  text ".TID" at 2793.5,-859 h60
  text "PLOT NAME =" at -228.5,-1064.34 h60
  text ".plot_File_Name" at 577,-1064.34 h60
  text "GENERATED    :" at 2250,-1064.34 h60
  text ".Print_Date" at 3119.5,-1064.34 h60
  text ".Print_Time" at 3848.5,-1064.34 h60
  text "TEXAS INSTRUMENTS" at 5113,-1064.34 h60
M6 Assembly Bottom:
  lines w10: -292.5,-727.33 6309.5,-727.33 ; -290.5,-930.67 6309.5,-930.67 ; 1115.5,-1140.5 1115.5,-937.67 ; 1737.5,-727.33 1737.5,-524 ; 2577.5,-727.33 2577.5,-524 ; 3844.5,-1134 3844.5,-524 ; 4733.5,-1134 6309,-1134 6309,-524 -292.5,-524 -292.5,-1134 2304.5,-1134 6309.5,-1134 6309.5,-524
  text "COMPONENTS MARKED 'DNP' SHOULD NOT BE POPULATED." at 6102,-318 h60
  text ".VariantName" at 5058,-434 h60
  text "ASSEMBLY VARIANT:" at 6097,-434 h60
  text ".VersionControl_RevNumber" at 1035.5,-656.17 h60
  text "SVN REV:" at 1541.5,-656.17 h60
  text ".PCB_Rev" at 2088,-656.17 h60
  text "REV:" at 2379.5,-656.17 h60
  text ".PRJ_Number" at 3224,-656.17 h60
  text "BOARD #:" at 3769.5,-656.17 h60
  text "PCB VIEWED FROM BOTTOM SIDE" at 6246,-656.17 h60
  text ".TID" at 3224,-859.5 h60
  text "TID #:" at 3769.5,-859.5 h60
  text "TEXAS INSTRUMENTS" at 904.5,-1064.84 h60
  text ".Print_Time" at 2169,-1064.84 h60
  text ".Print_Date" at 2898,-1064.84 h60
  text "GENERATED    :" at 3767.5,-1064.84 h60
  text ".plot_File_Name" at 5440.5,-1064.84 h60
  text "PLOT NAME =" at 6246,-1064.84 h60
M9 Title Sheet:
  drawing of 57 lines, arcs and shapes, not listed
  text "1" at 739.84,8036.5 h70
  text "2" at 3235.5,8036.5 h70
  text "3" at 5724.84,8036.5 h70
  text "4" at 8231.51,8036.5 h70
  text "5" at 10730.5,8036.5 h70
  text "6" at 13235.5,8036.5 h70
  text "A" at -416.5,6893.5 h70
  text "A" at 14383.5,6893.5 h70
  text "B" at -416.5,4513.5 h70
  text "B" at 14383.5,4513.5 h70
  text "C" at -416.5,2138.5 h70
  text "C" at 14383.5,2138.5 h70
  text "PROJECT TITLE:" at 11343.5,277.5 h45
  text ".TIDA-01007" at 11393.5,144.17 h70
  text "DESIGNED FOR:" at 11343.5,-23.5 h45
  text ".PRJ_Customer" at 11393.5,-163.5 h70
  text "D" at -416.5,-231.5 h70
  text "D" at 14383.5,-231.5 h70
  text "FILE NAME:" at 11343.5,-323.5 h45
  text ".PCB_File_Name_No_Path" at 11393.5,-443.5 h70
  text "Texas Instruments (TI) and/or its licensors do not warrant the accuracy or completeness of this specification" at 6374,-605.34 h45
  text "ENGINEER:" at 11343.5,-613.5 h45
  text "LAYOUT BY:" at 12848.5,-613.5 h45
  text "or any information contained therein. TI and/or its licensors do not warrant that this design will meet" at 6329.01,-718 h45
  text ".Summer Su" at 11393.5,-768.49 h70
  text ".PCB_Layout" at 12899,-768.49 h70
  text "the specifications, will be suitable for your application or fit for any particular purpose, or will operate in" at 6329.01,-830.67 h45
  text ".Layer_Name" at 577,-858.49 h60
  text "ALTIUM DESIGNER VERSION:" at 12848.5,-923.5 h45
  text "an implementation. TI and/or its licensors do not warrant that the design is production worthy. You should" at 6329.01,-943.33 h45
  text "completely validate and test your design implementation to confirm the system functionality for your application." at 6374,-1056 h45
  text ".print_Scale" at 11393.5,-1056.83 h70
  text ".Application_BuildNumber" at 12899,-1056.83 h70
  text "1" at 739.84,-1263.5 h70
  text "2" at 3235.5,-1263.5 h70
  text "3" at 5724.84,-1263.5 h70
  text "4" at 8231.51,-1263.5 h70
  text "5" at 10730.5,-1263.5 h70
  text "6" at 13235.5,-1263.5 h70
M10 Fab Notes:
  drawing of 185 lines, arcs and shapes, not listed
  text "DESIGN INFORMATION" at 12381.02,5910 h60
  text "MIN. TRACK WIDTH:" at 11736.46,5730 h60
  text "8" at 12832.7,5730 h60
  text "MIL" at 12987.46,5730 h60
  text "MIN. CLEARANCE:" at 11736.46,5598 h60
  text "0.2" at 12772.7,5598 h60
  text "mm" at 12987.46,5598 h60
  text "MIN. VIA PAD SIZE:" at 11736.46,5466 h60
  text "24" at 12802.71,5466 h60
  text "MIL" at 12987.46,5466 h60
  text "0.05mm (2MIL)" at 12431.46,5324.29 h60
  text "MINIMUM ANNULAR RING" at 11407.23,5320 h60
  text "EXTERNAL" at 13139.46,5320 h60
  text "PER" at 11607.23,5202 h60
  text "IPC-D-275 CLASS 2 LEVEL C" at 11827.23,5202 h60
  text "MIL, HOLES" at 13315.46,5089.71 h60
  text "+/-" at 12923,5089 h60
  text "+/-" at 13777,5089 h60
  text "REGISTRATION TOLERANCES:" at 11407.23,5084 h60
  text "METAL" at 12607,5084 h60
  text "5" at 13183.2,5084 h60
  text "3" at 14016.2,5084 h60
  text "MIL" at 14132.46,5084 h60
  text "MATERIAL:" at 11332.46,4874.54 h60
  text "FR-4 High Tg" at 12318.9,4734.21 h60
  text "FR-408" at 11753.46,4725.64 h60
  text "X" at 12165.46,4725.64 h60
  text "OTHER" at 13241.46,4725.64 h60
  text "62 MIL (1.6mm) +/-10%" at 12073.56,4562.92 h60
  text "THICKNESS:" at 11407.23,4558.64 h60
  text "X" at 11945.4,4558.64 h60
  text "OTHER" at 13358.46,4558.64 h60
  text "TOLERANCE:" at 11407.23,4400.64 h60
  text "X" at 12246.53,4400.64 h60
  text "ANSI IPC-6012 TYPE 3 CLASS 2" at 12433.48,4400.64 h60
  text "OTHER +/-" at 12433.46,4244.64 h60
  text "BOW & TWIST:" at 11407.23,4087.64 h60
  text "X" at 12246.53,4087.64 h60
  text "ANSI IPC-6012 TYPE 3 CLASS 2" at 12433.48,4087.64 h60
  text "OTHER +/-" at 12433.46,3929.13 h60
  text "DRILLING:" at 11332.46,3790.64 h60
  text "REFERENCE:" at 11407.23,3673.64 h60
  text "X" at 12055.46,3673.64 h60
  text "AS SHOWN" at 12242.46,3673.64 h60
  text "X" at 12956.46,3673.64 h60
  text "NC_DRILL FILES" at 13093.46,3673.64 h60
  text "PTH MIN COPPER THICKNESS:" at 11407.23,3515.64 h60
  text "X" at 12757.46,3515.64 h60
  text "1MIL" at 12894.46,3515.64 h60
  text "OTHER" at 13391.46,3515.64 h60
  text "BOARD FINISH:" at 11332.46,3356.64 h60
  text "SILKSCREEN:" at 11487.68,3238.64 h60
  text "X" at 12436.46,3238.64 h60
  text "TOP" at 12562.46,3238.64 h60
  text "X" at 12946.46,3238.64 h60
  text "BOTTOM" at 13073.46,3238.64 h60
  text "SILKSCREEN COLOR:" at 11487.68,3071.64 h60
  text "X" at 12435.42,3071.64 h60
  text "WHITE" at 12562.46,3071.64 h60
  text "OTHER" at 13073.46,3071.64 h60
  text "SOLDER RESIST COLOR:" at 11487.68,2901.64 h60
  text "X" at 12650,2750 h60
  text "GREEN" at 12182.46,2742.44 h60
  text "BLUE" at 12773.46,2742.44 h60
  text "OTHER" at 13311.46,2742.44 h60
  text "IMMERSION GOLD (ENIG)" at 12393.46,2553.92 h60
  text "ENEPIG" at 13731,2550.64 h60
  text "SURFACE FINISH:" at 11332.46,2549.64 h60
  text "X" at 12206.51,2549.64 h60
  text "IMM. TIN/SILVER OR EQUIV" at 11662,2392.64 h60
  text "OTHER" at 13093.46,2392.64 h60
  text "ARRAY/PANEL:" at 11332.46,2213.64 h60
  text "CUT AND TRIM PER MECH LAYER 1" at 12393.46,2209.35 h60
  text "N.C. ROUTE" at 12393.46,2057.64 h60
  text "X" at 13072.46,2057.64 h60
  text "V. SCORE" at 13259.46,2057.64 h60
  text "CERTIFICATION:" at 11332.46,1920.64 h60
  text "MATERIALS AND WORKMANSHIP FOR ALL PCBS" at 12057.46,1920.64 h60
  text "TO MEET OR EXCEED THE REQUIREMENTS OF:" at 12057.46,1822.64 h60
  text "X" at 11683.96,1686.13 h60
  text "ANSI IPC-A-600F CLASS ->" at 11822.96,1686.13 h60
  text "X" at 13462.02,1686.13 h60
  text "2" at 13580.96,1686.14 h60
  text "1" at 13265.96,1684.64 h60
  text "3" at 13934.96,1684.64 h60
  text "X" at 11686.02,1526.64 h60
  text "UL 94V-0" at 11822.96,1526.64 h60
  text "X" at 12498.02,1526.64 h60
  text "RoHS" at 12634.96,1526.64 h60
  text "OTHER" at 13279.36,1526.64 h60
  text "PER ORDER" at 13676.42,1526.64 h60
  text "ADDITIONAL REQUIREMENTS:" at 11332.46,1385.64 h60
  text "MICROSECTION:" at 11407.23,1270.64 h60
  text "YES" at 12312.96,1270.64 h60
  text "REQUIRED" at 13174.46,1114.49 h60
  text "BARE BOARD ELEC. TEST:" at 11407.23,1111.64 h60
  text "NONE" at 12712.96,1111.64 h60
  text "X" at 13047.46,1111.64 h60
  text "PER ORDER" at 13766.46,1111.64 h60
  text "MANUFACTURER'S UL:" at 11407.23,954.64 h60
  text "RAIL" at 12572.96,950.35 h60
  text "METAL" at 13064.77,950.35 h60
  text "X" at 13440,950 h60
  text "SILK" at 13576.46,950.35 h60
  text ".Layer_Name" at 577,-858.49 h60
M11 Gerber Information:
  lines w10: -292,-930.17 6308,-930.17 ; -292,-726.83 6310,-726.83 ; -292,-523.5 -292,-1133.5 3713,-1133.5 6310,-1133.5 6310,-523.5 -291.5,-523.5 -291.5,-1133.5 1284,-1133.5 ; 2173,-1133.5 2173,-523.5 ; 3440,-726.83 3440,-523.5 ; 4280,-726.83 4280,-523.5 ; 4902,-1140 4902,-937.17
  text "ALL ARTWORK VIEWED FROM TOP SIDE" at -228.5,-655.67 h60
  text "BOARD #:" at 2248,-655.67 h60
  text ".PRJ_Number" at 2793.5,-655.67 h60
  text "REV:" at 3638,-655.67 h60
  text ".PCB_Rev" at 3929.5,-655.67 h60
  text "SVN REV:" at 4476,-655.67 h60
  text ".VersionControl_RevNumber" at 4982,-655.67 h60
  text "LAYER NAME =" at -228.5,-858.49 h60
  text "TID #:" at 2248,-859 h60
  text ".TID" at 2793.5,-859 h60
  text "PLOT NAME =" at -228.5,-1064.34 h60
  text ".plot_File_Name" at 577,-1064.34 h60
  text "GENERATED    :" at 2250,-1064.34 h60
  text ".Print_Date" at 3119.5,-1064.34 h60
  text ".Print_Time" at 3848.5,-1064.34 h60
  text "TEXAS INSTRUMENTS" at 5113,-1064.34 h60
M12 Stackup:
  drawing of 191 lines, arcs and shapes, not listed
  text "Layer" at 9790.58,7830 h60
  text "Name" at 10200.49,7830 h60
  text "Material" at 11130.23,7830 h60
  text "Thickness" at 11990,7830 h60
  text "Constant" at 12639.84,7830 h60
  text "Board Layer Stack" at 13209.7,7830 h60
  text "1" at 9790.58,7710 h60
  text "Top Overlay" at 10200.49,7710 h60
  text "2" at 9790.58,7590 h60
  text "Top Solder" at 10200.49,7590 h60
  text "Solder Resist" at 11130.23,7590 h60
  text "0.40mil" at 11990,7590 h60
  text "3.5" at 12639.84,7590 h60
  text "3" at 9790.58,7470 h60
  text "Top Layer" at 10200.49,7470 h60
  text "Copper" at 11130.23,7470 h60
  text "1.40mil" at 11990,7470 h60
  text "4" at 9790.58,7350 h60
  text "Dielectric1" at 10200.49,7350 h60
  text "FR-4" at 11130.23,7350 h60
  text "59.20mil" at 11990,7350 h60
  text "4.8" at 12639.84,7350 h60
  text "5" at 9790.58,7230 h60
  text "Bottom Layer" at 10200.49,7230 h60
  text "Copper" at 11130.23,7230 h60
  text "1.40mil" at 11990,7230 h60
  text "6" at 9790.58,7110 h60
  text "Bottom Solder" at 10200.49,7110 h60
  text "Solder Resist" at 11130.23,7110 h60
  text "0.40mil" at 11990,7110 h60
  text "3.5" at 12639.84,7110 h60
  text "7" at 9790.58,6990 h60
  text "Bottom Overlay" at 10200.49,6990 h60
  text ".Layer_Name" at 577,-858.49 h60
M13 Component Bodies Top:
  text ".Layer_Name" at 577,-858.49 h60
M14 Component Bodies Bottom:
  text ".Layer_Name" at 577,-858.49 h60
M15 Courtyards Top:
  text ".Layer_Name" at 577,-858.49 h60
M16 Courtyards Bottom:
  text ".Layer_Name" at 577,-858.49 h60
Drill Drawing:
  circle w1: c5557.8,3259.18 r20.74
  lines w1: 5537.05,2865.09 5578.54,2865.09 5578.54,2906.57 5537.05,2906.57 5537.05,2865.09 ; 5537.05,2989.53 5557.8,2999.91 5578.54,2989.53 5568.17,3010.28 5578.54,3031.02 5557.8,3020.65 5537.05,3031.02 5547.42,3010.28 5537.05,2989.53 ; 5537.05,3155.47 5578.54,3155.47 5557.8,3113.98 5537.05,3155.47
  lines w12: 5480,2827.75 7509.36,2827.75 ; 5480,3325.55 7509.36,3325.55 ; 5828.16,2703.3 5828.16,3450 ; 6170.27,2703.3 6170.27,3450 ; 6817.27,2703.3 6817.27,3450 ; 7086.62,2703.3 7086.62,3450 ; 5480,2703.3 7509.36,2703.3 7509.36,3450 5480,3450 5480,2703.3
  text "Symbol" at 5554.67,3362.89 h72
  text "Quantity" at 5865.5,3362.89 h72
  text "Finished Hole Size" at 6207.6,3362.89 h72
  text "Plated" at 6854.6,3362.89 h72
  text "Hole Type" at 7123.95,3362.89 h72
  text "17" at 5865.5,3238.44 h60
  text "7.87mil (0.200mm)" at 6207.6,3238.44 h60
  text "PTH" at 6854.6,3238.44 h60
  text "Round" at 7123.95,3238.44 h60
  text "1715" at 5865.5,3113.98 h60
  text "18.00mil (0.457mm)" at 6207.6,3113.98 h60
  text "PTH" at 6854.6,3113.98 h60
  text "Round" at 7123.95,3113.98 h60
  text "4" at 5865.5,2989.53 h60
  text "51.18mil (1.300mm)" at 6207.6,2989.53 h60
  text "PTH" at 6854.6,2989.53 h60
  text "Round" at 7123.95,2989.53 h60
  text "4" at 5865.5,2865.09 h60
  text "125.98mil (3.200mm)" at 6207.6,2865.09 h60
  text "PTH" at 6854.6,2865.09 h60
  text "Round" at 7123.95,2865.09 h60
  text "1740 Total" at 5865.5,2740.64 h60
  text ".Layer_Name" at 577,-858.49 h60

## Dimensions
0,-400 to 1000,-400 on M2 Board Dimensions
0,0 to 0,3450 on M2 Board Dimensions
0,0 to 4950,0 on M2 Board Dimensions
